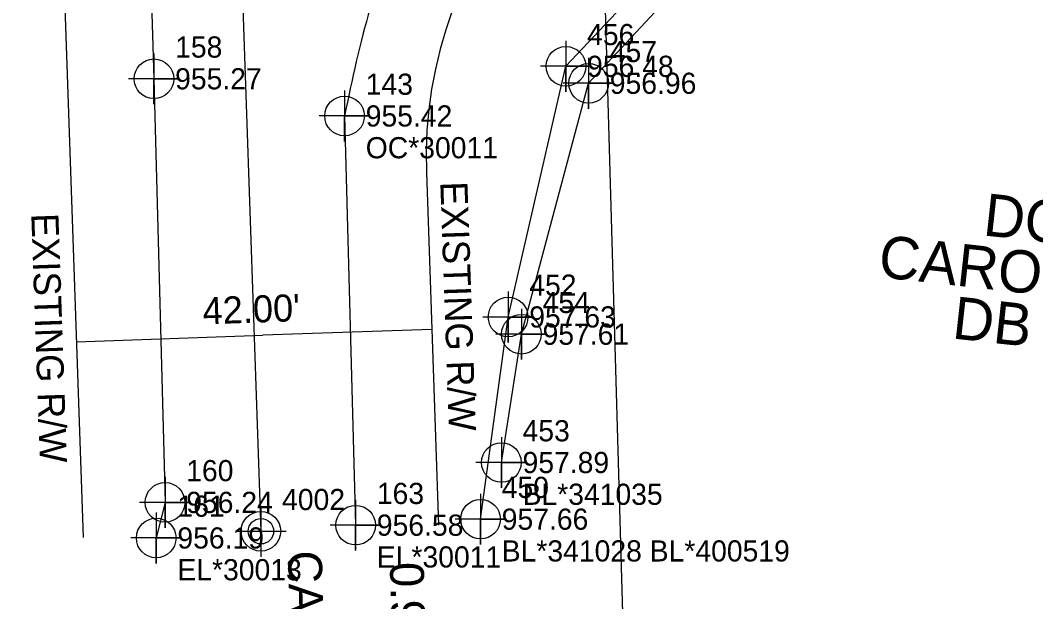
# Model space of a CAD drawing. Extents: x 1150279 to 1151282, y 654632 to 657999.
# Drawn here: x 1150547.5 to 1150667.5, y 657009.2 to 657077.9 of the extents above; entities that cross this region are included whole.
import ezdxf

# ---------------------------------------------------------------- set-up
doc = ezdxf.new("R2010")
doc.units = 0
for name, color, linetype in [('COGO Default Chain', 7, 'Continuous'), ('Cogo Default Point CELL', 7, 'Continuous'), ('COGO Default Point Number', 7, 'Continuous'), ('Exist Horizontal Alignment', 7, 'Continuous'), ('Exist Horizontal Alignment Station Label', 7, 'Continuous'), ('Exist Other Culture Fence Line', 7, 'Continuous'), ('Exist Other Culture Fence Line Cogo Comment', 7, 'Continuous'), ('Exist Other Culture Fence Line Cogo Elevation', 7, 'Continuous'), ('Exist Other Culture Fence Line Cogo Number', 7, 'Continuous'), ('Exist Other Culture Fence Line Cogo Point CELL', 7, 'Continuous'), ('Exist Property Deed Book Text', 7, 'Continuous'), ('Exist Property Owner Text', 7, 'Continuous'), ('Exist Right of Way Line', 7, 'Continuous'), ('Exist Right of Way Line Text', 7, 'Continuous'), ('Exist Right of Way Width CELL', 7, 'Continuous'), ('Exist Roads EOP', 7, 'Continuous'), ('Exist Roads EOP Cogo Comment', 7, 'Continuous'), ('Exist Roads EOP Cogo Elevation', 7, 'Continuous'), ('Exist Roads EOP Cogo Number', 7, 'Continuous'), ('Exist Roads EOP Cogo Point CELL', 7, 'Continuous'), ('Exist Roads EOP Text', 7, 'Continuous')]:
    doc.layers.add(name, color=color, linetype=linetype)

msp = doc.modelspace()

# ---------------------------------------------------------------- linework, layer by layer
at = {"layer": 'COGO Default Chain'}
for p, q in [((1150568.54, 657231.15), (1150575.96, 657017.52)), ((1150663.4, 655450.47), (1150614.76, 657145.26))]:
    msp.add_line(p, q, dxfattribs=at)
at = {"layer": 'Cogo Default Point CELL'}
for points in [[(1150575.96, 657020.52), (1150575.96, 657017.52)], [(1150572.96, 657017.52), (1150575.96, 657017.52)], [(1150575.96, 657017.52), (1150578.96, 657017.52)], [(1150575.96, 657017.52), (1150575.96, 657014.52)]]:
    msp.add_lwpolyline(points, dxfattribs=at)
msp.add_circle((1150575.96, 657017.52), 2.34, dxfattribs=at)
at = {"layer": 'Exist Horizontal Alignment'}
msp.add_line((1150568.54, 657231.15), (1150575.96, 657017.52), dxfattribs=at)
at = {"layer": 'Exist Horizontal Alignment Station Label'}
msp.add_circle((1150575.96, 657017.52), 1.5, dxfattribs=at)
at = {"layer": 'Exist Other Culture Fence Line'}
for points in [[(1150604.36, 657025.64), (1150606.72, 657040.79), (1150614.66, 657070.42), (1150624.72, 657081.25), (1150654.48, 657089.88), (1150677.88, 657097.66), (1150678.26, 657106.74)], [(1150601.9, 657018.95), (1150605.15, 657042.82), (1150611.98, 657072.42), (1150621.9, 657083), (1150637.68, 657096.18), (1150678.11, 657106.44)]]:
    msp.add_lwpolyline(points, dxfattribs=at)
at = {"layer": 'Exist Other Culture Fence Line Cogo Point CELL'}
for points in [[(1150611.98, 657075.42), (1150611.98, 657069.42), (1150611.98, 657072.42), (1150614.98, 657072.42), (1150608.98, 657072.42)], [(1150614.66, 657073.42), (1150614.66, 657067.42), (1150614.66, 657070.42), (1150617.66, 657070.42), (1150611.66, 657070.42)], [(1150605.15, 657045.82), (1150605.15, 657039.82), (1150605.15, 657042.82), (1150608.15, 657042.82), (1150602.15, 657042.82)], [(1150606.72, 657043.79), (1150606.72, 657037.79), (1150606.72, 657040.79), (1150609.72, 657040.79), (1150603.72, 657040.79)], [(1150604.36, 657028.64), (1150604.36, 657022.64), (1150604.36, 657025.64), (1150607.36, 657025.64), (1150601.36, 657025.64)], [(1150601.9, 657021.95), (1150601.9, 657015.95), (1150601.9, 657018.95), (1150604.9, 657018.95), (1150598.9, 657018.95)]]:
    msp.add_lwpolyline(points, dxfattribs=at)
for centre in [(1150611.98, 657072.42), (1150614.66, 657070.42), (1150605.15, 657042.82), (1150606.72, 657040.79), (1150604.36, 657025.64), (1150601.9, 657018.95)]:
    msp.add_circle(centre, 2.34, dxfattribs=at)
at = {"layer": 'Exist Right of Way Line'}
for p, q in [((1150547.55, 657230.42), (1150554.98, 657016.79)), ((1150595.5, 657059.88), (1150596.95, 657018.25))]:
    msp.add_line(p, q, dxfattribs=at)
msp.add_arc((1150645.47, 657061.62), 50, 94.3102, 181.9914, dxfattribs=at)
at = {"layer": 'Exist Right of Way Width CELL'}
for p in [(1150554.17, 657039.89), (1150596.15, 657041.35)]:
    msp.add_line(p, (1150576.2, 657040.66), dxfattribs=at)
at = {"layer": 'Exist Roads EOP'}
msp.add_line((1150585.84, 657066.56), (1150587.15, 657018.24), dxfattribs=at)
msp.add_lwpolyline([(1150555.6, 657230.84), (1150557.81, 657218.94), (1150559.89, 657167.47), (1150561.73, 657122.25), (1150563.33, 657070.95), (1150564.64, 657020.93), (1150563.6, 657016.73)], dxfattribs=at)
msp.add_spline([(1150646.28, 657116.94), (1150622.67, 657111.56), (1150606.22, 657102.96), (1150594, 657090.81), (1150585.84, 657066.56)], degree=3, dxfattribs=at)
at = {"layer": 'Exist Roads EOP Cogo Point CELL'}
for points in [[(1150563.33, 657073.95), (1150563.33, 657067.95), (1150563.33, 657070.95), (1150566.33, 657070.95), (1150560.33, 657070.95)], [(1150585.84, 657069.56), (1150585.84, 657063.56), (1150585.84, 657066.56), (1150588.84, 657066.56), (1150582.84, 657066.56)], [(1150564.64, 657023.93), (1150564.64, 657017.93), (1150564.64, 657020.93), (1150567.64, 657020.93), (1150561.64, 657020.93)], [(1150587.15, 657021.24), (1150587.15, 657015.24), (1150587.15, 657018.24), (1150590.15, 657018.24), (1150584.15, 657018.24)], [(1150563.6, 657019.73), (1150563.6, 657013.73), (1150563.6, 657016.73), (1150566.6, 657016.73), (1150560.6, 657016.73)]]:
    msp.add_lwpolyline(points, dxfattribs=at)
for centre in [(1150563.33, 657070.95), (1150585.84, 657066.56), (1150564.64, 657020.93), (1150587.15, 657018.24), (1150563.6, 657016.73)]:
    msp.add_circle(centre, 2.34, dxfattribs=at)

# ---------------------------------------------------------------- texts
at = {"layer": 'COGO Default Point Number'}
msp.add_text('4002', height=2.5, dxfattribs=at).set_placement((1150578.46, 657020.02))
at = {"layer": 'Exist Other Culture Fence Line Cogo Comment'}
for s, p in [('BL*341035', (1150606.86, 657020.64)), ('BL*341028 BL*400519', (1150604.4, 657013.95))]:
    msp.add_text(s, height=2.5, dxfattribs=at).set_placement(p)
at = {"layer": 'Exist Other Culture Fence Line Cogo Elevation'}
for s, p in [('956.48', (1150614.48, 657071.17)), ('956.96', (1150617.16, 657069.17)), ('957.63', (1150607.65, 657041.58)), ('957.61', (1150609.22, 657039.54)), ('957.89', (1150606.86, 657024.39)), ('957.66', (1150604.4, 657017.7))]:
    msp.add_text(s, height=2.5, dxfattribs=at).set_placement(p)
at = {"layer": 'Exist Other Culture Fence Line Cogo Number'}
for s, p in [('456', (1150614.48, 657074.92)), ('457', (1150617.16, 657072.92)), ('452', (1150607.65, 657045.33)), ('454', (1150609.22, 657043.29)), ('453', (1150606.86, 657028.14)), ('450', (1150604.4, 657021.45))]:
    msp.add_text(s, height=2.5, dxfattribs=at).set_placement(p)
at = {"layer": 'Exist Property Deed Book Text'}
msp.add_text('DB 748 PG 810', height=5, rotation=353.6867, dxfattribs=at).set_placement((1150657.48, 657040.3))
at = {"layer": 'Exist Property Owner Text'}
for s, p in [('DOUGLAS H. &', (1150661.13, 657052.47)), ('CAROL S. NETHAWAY', (1150648.74, 657047.56))]:
    msp.add_text(s, height=5, rotation=353.6867, dxfattribs=at).set_placement(p)
at = {"layer": 'Exist Right of Way Line Text'}
for p in [(1150597.14, 657058.77), (1150548.84, 657055.02)]:
    msp.add_text('EXISTING R/W', height=3.2, rotation=271.9914, dxfattribs=at).set_placement(p)
at = {"layer": 'Exist Right of Way Width CELL'}
msp.add_text("42.00'", height=3.2, rotation=1.9914, dxfattribs=at).set_placement((1150569.12, 657041.94))
at = {"layer": 'Exist Roads EOP Cogo Comment'}
for s, p in [('OC*30011', (1150588.34, 657061.56)), ('EL*30011', (1150589.65, 657013.24)), ('EL*30013', (1150566.1, 657011.73))]:
    msp.add_text(s, height=2.5, dxfattribs=at).set_placement(p)
at = {"layer": 'Exist Roads EOP Cogo Elevation'}
for s, p in [('955.27', (1150565.83, 657069.7)), ('955.42', (1150588.34, 657065.31)), ('956.24', (1150567.14, 657019.68)), ('956.58', (1150589.65, 657016.99)), ('956.19', (1150566.1, 657015.48))]:
    msp.add_text(s, height=2.5, dxfattribs=at).set_placement(p)
at = {"layer": 'Exist Roads EOP Cogo Number'}
for s, p in [('158', (1150565.83, 657073.45)), ('143', (1150588.34, 657069.06)), ('160', (1150567.14, 657023.43)), ('163', (1150589.65, 657020.74)), ('161', (1150566.1, 657019.23))]:
    msp.add_text(s, height=2.5, dxfattribs=at).set_placement(p)
at = {"layer": 'Exist Roads EOP Text'}
for s, p in [('CAMP CREEK RD.', (1150579.14, 657015.19)), ('0.98 MILES +/-', (1150591.18, 657013.83))]:
    msp.add_text(s, height=4, rotation=271.5458, dxfattribs=at).set_placement(p)

doc.saveas('drawing.dxf')
